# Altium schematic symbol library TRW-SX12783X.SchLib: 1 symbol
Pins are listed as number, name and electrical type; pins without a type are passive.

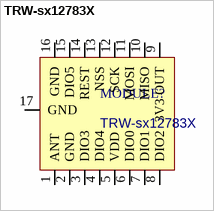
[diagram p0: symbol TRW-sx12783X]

## TRW-sx12783X
designator MODULE?
LORA 470mhz 1-2W RF MODULE
footprint TRW-SX12783S SMD
footprint TRW-SX12783X (DIP)
pins: 1 ANT, 2 GND, 3 DIO3, 4 DIO4, 5 VDD, 6 DIO0, 7 DIO1, 8 DIO2, 9 3V3 OUT, 10 MISO, 11 MOSI, 12 SCK, 13 NSS, 14 REST, 15 DIO5, 16 GND, 17 GND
